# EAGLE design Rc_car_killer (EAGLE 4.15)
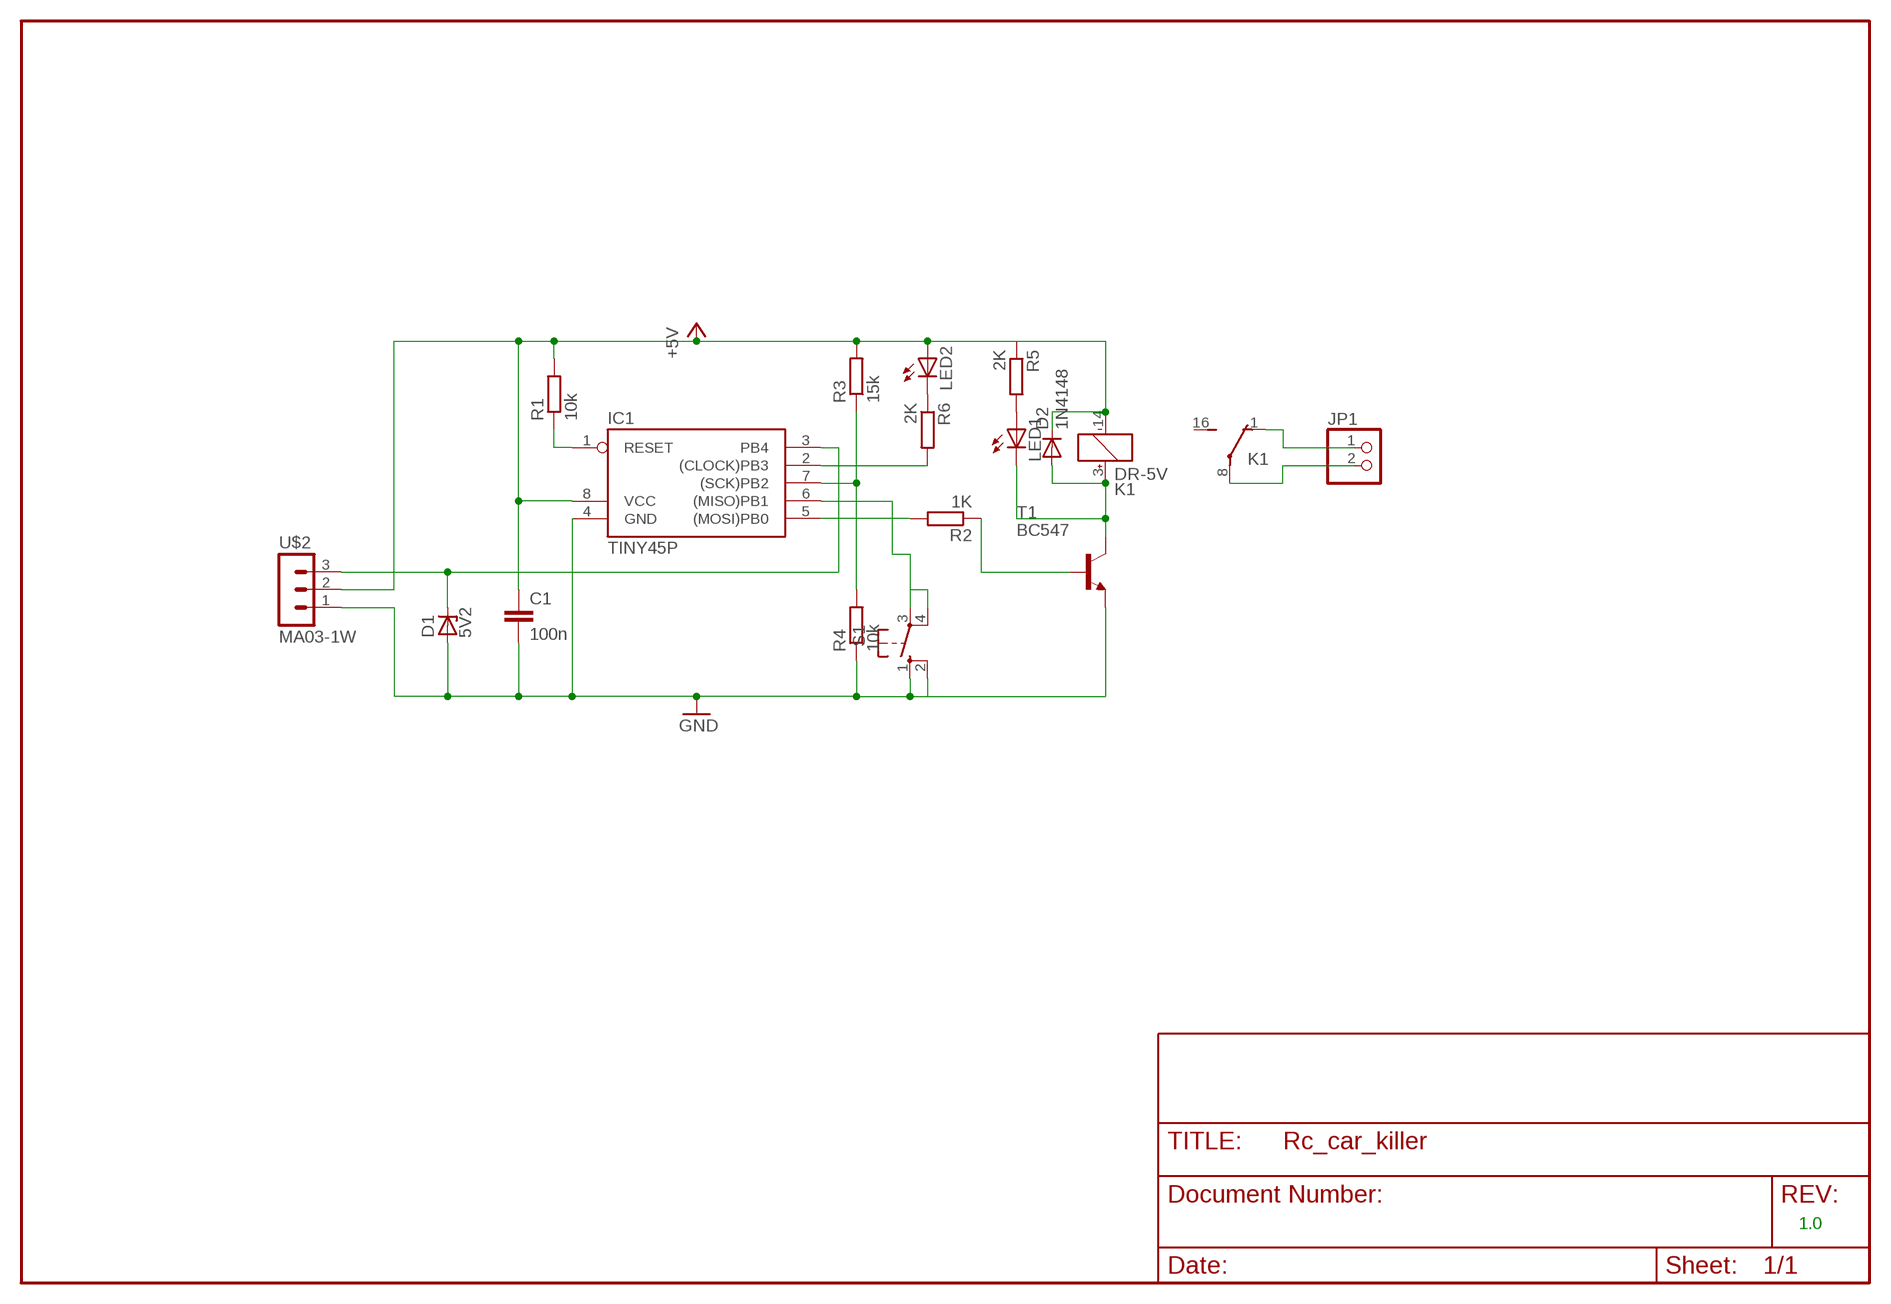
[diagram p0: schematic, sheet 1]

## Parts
C1  100n  C-EU025-025X050  [C025-025X050]
D1  5V2  ZENER-DIODEZD-7.5  [ZDIO-7.5]
D2  1N4148  [DO35-10]
IC1  TINY45P  [DIL08]
JP1  PINHD-1X2  [1X02]
K1  DR-5V  [DR-1]
LED1  LED3MM  [LED3MM]
LED2  LED3MM  [LED3MM]
R1  10k  R-EU_  [0207/10_GROOT]
R2  1K  R-EU_  [0207/10_GROOT]
R3  15k  R-EU_  [0207/10_GROOT]
R4  10k  R-EU_  [0207/10_GROOT]
R5  2K  R-EU_  [0207/10_GROOT]
R6  2K  R-EU_  [0207/10_GROOT]
S1  10-XX-REVERSED  [B3F-10XX]
T1  BC547  [TO92]
U$2  MA03-1W  [MA03-1W]

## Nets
+5V [Vcc]: C1.1 D2.C IC1.8(VCC) K1.14(-1:-) LED2.A R1.2 R3.2 R5.1 U$2.2
GND [gnd]: C1.2 D1.A IC1.4(GND) R4.1 S1.1(S) S1.2(S1) T1.1(E) U$2.1
N$1: IC1.7((SCK)PB2) R3.1 R4.2
N$2: IC1.1(RESET) R1.1
N$3: IC1.5((MOSI)PB0) R2.2
N$4: LED1.A R5.2
N$5: IC1.6((MISO)PB1) S1.3(P) S1.4(P1)
N$6: D1.C IC1.3(PB4) U$2.3
N$8: D2.A K1.3(-1:+) LED1.K(C) T1.3(C)
N$9: LED2.K(C) R6.1
N$10: IC1.2((CLOCK)PB3) R6.2
N$11: R2.1 T1.2(B)
N$12: JP1.2 K1.8(-2:P)
N$13: JP1.1 K1.1(-2:O)
Unconnected: K1.16(-2:S)

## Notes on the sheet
- 1.0

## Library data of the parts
C1 = rcl:C-EU: CAPACITOR, European symbol
D1 = diode:ZENER-DIODE: Z-Diode
D2 = diode:1N4148: DIODE
IC1 = Evert:TINY45: MICROCONTROLLER 1K ROM 128 bytes RAM 128 bytes EEPROM
JP1 = pinhead:PINHD-1X2: PIN HEADER
K1 = relay:DR-*V: HIGHLY RELIABLE MINIATURE DIP RELAYS NAiS Source: www.mew-europe.com/ac/download/ datasheet/relay/dr_en.pdf
LED1 LED2 = led:LED: LED
R1-R6 = rcl:R-EU_: RESISTOR, European symbol
S1 = Evert:10-XX-REVERSED: OMRON SWITCH
T1 = transistor:BC547: NPN TRANSISTOR
U$2 = con-lstb:MA03-1W

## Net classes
0 default: width 0.61 mm, drill 0.051 mm
1 Vcc: width 0.5 mm, drill 0.051 mm
2 gnd: width 0.2 mm, drill 0.051 mm

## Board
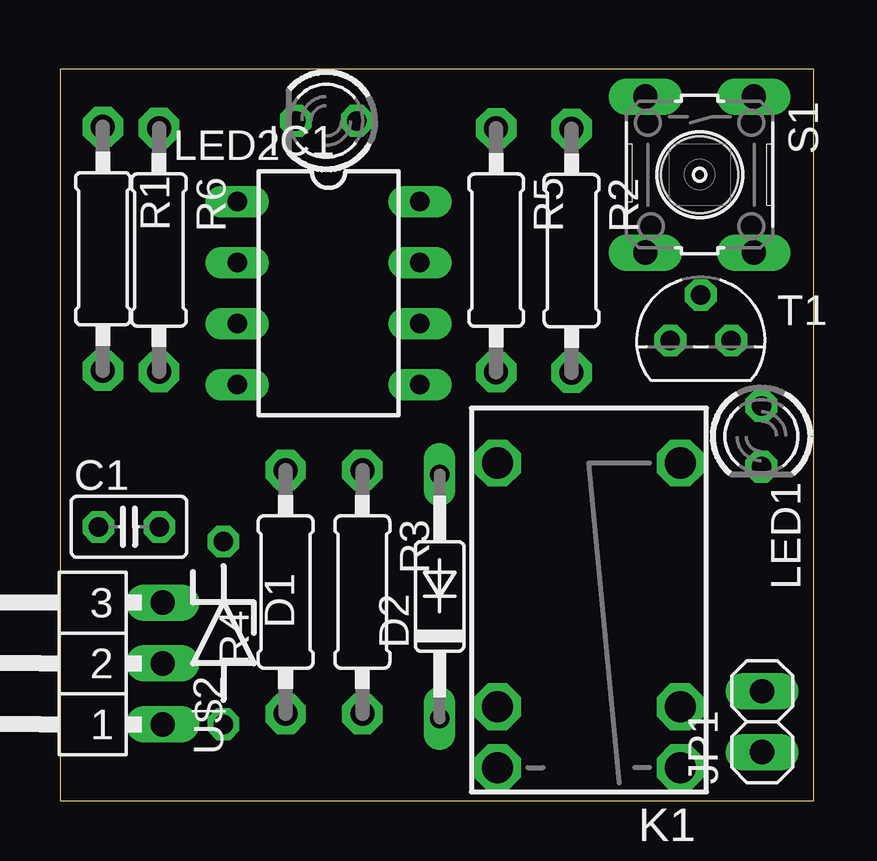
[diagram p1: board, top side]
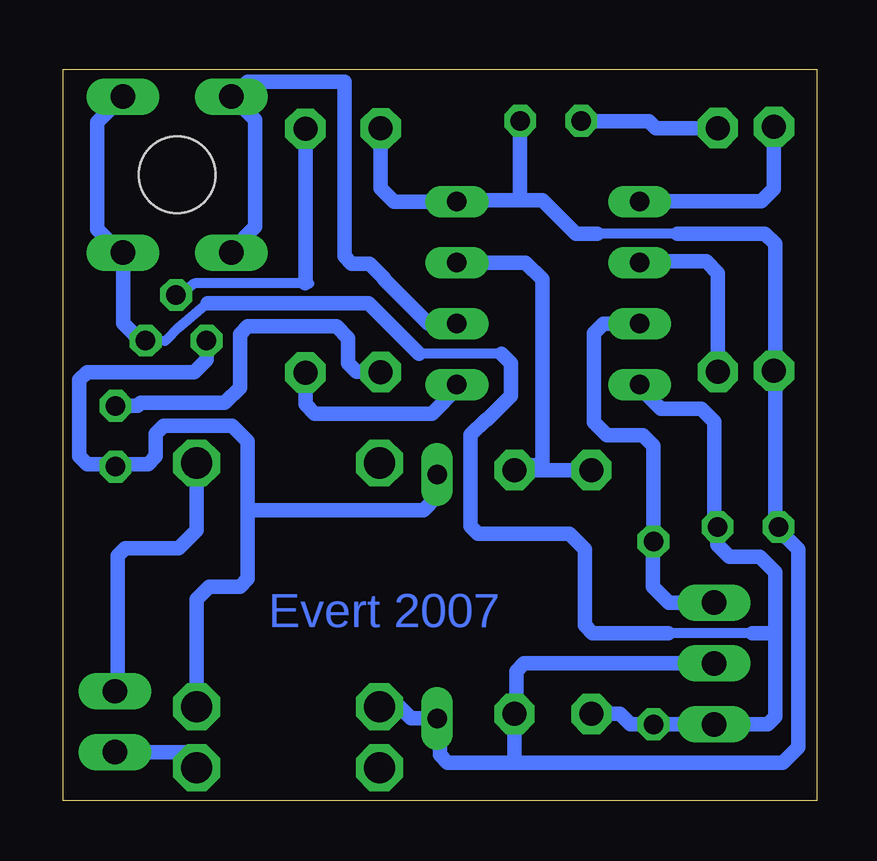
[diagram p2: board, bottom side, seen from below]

Size 31.42 x 30.47 mm. Coordinates in mm from the lower left corner, seen from the top.
Outline: 0,0 31.42,0 31.42,30.47 0,30.47 0,0
Copper layers (1*16): Top 0.035mm / dielectric 1.5mm / Bottom 0.035mm
Design rules "default": minimum track width 10mil, minimum drill 24mil, track to track 8mil, track to pad 8mil, pad to pad 8mil, via to via 8mil, smd to smd 8mil, copper to edge 20mil, drill to drill 8mil, minimum pad ring 10mil, minimum via ring 8mil, stop-mask expansion 4mil, vias tented up to drill 0mil, thermal gap 10mil

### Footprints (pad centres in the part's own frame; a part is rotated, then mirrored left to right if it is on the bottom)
C025-025X050 = drill 0.813 octagon: 1 -1.27,0; 2 1.27,0
ZDIO-7.5 = drill 0.813 octagon: A 3.81,0; C -3.81,0
DO35-10 = drill 0.813 long: A 5.08,0; C -5.08,0
DIL08 = drill 0.813 long: 1 -3.81,-3.81; 2 -1.27,-3.81; 3 1.27,-3.81; 4 3.81,-3.81; 5 3.81,3.81; 6 1.27,3.81; 7 -1.27,3.81; 8 -3.81,3.81
1X02 = drill 1.016 long: 1 -1.27,0; 2 1.27,0
DR-1 = drill 1.3 octagon: 1 -8.89,-3.81; 3 -6.35,-3.81; 8 3.81,-3.81; 9 3.81,3.81; 14 -6.35,3.81; 16 -8.89,3.81
LED3MM = drill 0.813 octagon: A -1.27,0; K 1.27,0
0207/10_GROOT = drill 1 pad 1.676 octagon: 1 -5.08,0; 2 5.08,0
B3F-10XX = drill 1.016 long: 1 -3.251,2.261; 2 3.251,2.261; 3 -3.251,-2.261; 4 3.251,-2.261 | hole 3.2: 0,0
TO92 = drill 0.813 octagon: 1 1.27,0; 2 0,1.905; 3 -1.27,0
MA03-1W = drill 1.016 long: 1 -2.54,0; 2 0,0; 3 2.54,0

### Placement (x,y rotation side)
C1  2.88,11.4 0 top
D1  6.81,6.99 270 top
D2  15.83,8.5 90 top
IC1  11.2,21.14 270 top
JP1  29.27,3.28 90 top
K1  22.05,10.26 90 top
LED1  29.24,15.18 270 top
LED2  11.1,28.32 180 top
R1  1.79,22.99 270 top
R2  21.33,22.91 270 top
R3  12.61,8.69 270 top
R4  9.41,8.69 90 top
R5  18.19,22.93 270 top
R6  4.13,22.94 270 top
S1  26.67,26.08 270 top
T1  26.72,19.16 0 top
U$2  4.28,5.71 90 top

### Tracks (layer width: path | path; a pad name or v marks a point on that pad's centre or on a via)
+5V
  Bottom 0.406: 5.81,23.61 9.16,23.61
  Bottom 0.61: 1.72,11.4 C1.1 | 1.72,11.4 1.74,11.43 | 1.72,11.4 0.79,10.47 0.79,2.22 1.42,1.58 12.54,1.58 | 12.54,1.58 15.39,1.58 15.71,1.9 15.71,3.3 D2.C 16.92,3.42 17.4,3.91 18.22,3.91 18.23,3.89 K1.14 | 12.54,1.58 12.61,1.65 R3.2 12.61,3.56 12.54,3.49 12.54,5.39 12.22,5.71 U$2.2 | R1.2 1.78,17.25 1.76,17.22 1.74,17.24 | C1.1 | 1.74,17.24 1.74,11.54 C1.1 | 1.74,17.24 1.74,23.19 2.17,23.61 5.81,23.61 | 9.16,23.61 10.06,23.61 11.45,25.01 12.3,25.01 | IC1.8 15.05,24.91 | IC1.8 17.63,24.95 18.19,25.51 18.19,27.96 18.19,27.97 R5.1 | 12.3,25.01 14.95,25.01 IC1.8 | 12.3,25.01 12.3,25.11 12.37,25.18 LED2.A
GND
  Bottom 0.406: S1.2 29.04,22.83 | 27.88,19.12 27.93,19.16 T1.1 27.18,19.14 26.58,19.73 26.64,19.68 25.4,20.71 | 2.69,6.98 6.18,6.98 | 16.56,18.62 16.6,18.62 | 13.15,18.62 16.56,18.62 | 16.56,18.62 16.56,18.6
  Bottom 0.61: S1.1 30,28.25 30,23.81 29.02,22.83 S1.2 28.93,19.88 28.09,19.04 T1.1 | 6.18,6.98 9.36,6.98 9.68,7.3 9.68,10.47 10.31,11.11 14.12,11.11 14.44,11.43 14.44,15.24 13.81,15.87 13.75,15.87 12.75,16.87 12.75,18.22 13.15,18.62 | R4.1 8.21,3.61 7.77,3.17 D1.A U$2.1 2.06,3.17 1.74,3.49 1.74,6.98 | 1.74,6.98 1.74,9.52 2.38,10.16 3.64,10.16 4.14,10.66 C1.2 4.26,11.4 4.28,11.43 4.28,15.79 4.81,16.32 6.51,16.32 7.39,17.2 IC1.4 | 1.74,6.98 2.69,6.98 | 25.4,20.71 18.69,20.71 16.6,18.62
N$1
  Bottom 0.61: 12.54,13.97 12.61,13.89 R3.1 | R4.2 12.34,13.77 12.54,13.97 | 12.54,13.97 11.45,13.97 11.45,21.71 12.15,22.41 14.95,22.41 15,22.36 15.01,22.37 IC1.7
N$2
  Bottom 0.61: R1.1 1.79,25.49 2.32,24.96 7.31,24.96 7.32,24.95 IC1.1
N$3
  Bottom 0.61: R2.2 21.33,16.51 20.94,16.12 16.05,16.12 15,17.17 15.01,17.18 IC1.5
N$4
  Bottom 0.61: LED1.A 28.32,16.45 28.2,16.57 24.7,16.57 24.06,17.2 24.06,19.44 23.74,19.75 20.03,19.75 19.54,19.27 19.54,18.22 19.19,17.87 18.19,17.87 R5.2
N$5
  Bottom 0.61: 24.38,29.32 24.39,29.33 S1.3 | 24.38,29.32 23.74,29.95 19.7,29.95 19.7,22.67 19.39,22.36 18.64,22.36 18.04,21.77 18.04,21.71 17.54,21.21 | 24.38,29.32 | 24.38,29.32 23.42,28.36 23.42,23.9 24.41,22.91 S1.4 | IC1.6 16.2,19.87 17.54,21.21 | 17.54,21.21
N$6
  Bottom 0.61: U$2.3 6.18,8.25 6.84,8.92 6.84,10.83 D1.C 6.81,14.77 7.26,15.22 8.76,15.22 9.31,15.77 9.31,19.47 8.91,19.87 7.36,19.87 IC1.3
N$8
  Bottom 0.61: K1.3 25.86,8.39 25.33,8.92 24.06,8.92 23.74,9.24 23.74,12.11 | 23.74,12.11 23.74,14.97 24.38,15.61 27.24,15.61 27.56,15.29 27.56,14.34 27.88,14.02 29.16,14.02 | D2.A 15.83,12.68 16.41,12.11 23.74,12.11 | T1.3 25.45,18.36 25.97,17.84 30.43,17.84 30.75,17.52 30.75,14.34 30.43,14.02 29.16,14.02 | 29.16,14.02 29.24,13.93 LED1.K
N$9
  Bottom 0.61: R6.1 6.72,28.02 7.01,28.31 9.76,28.31 9.77,28.32 LED2.K
N$10
  Bottom 0.61: R6.2 4.13,21.98 4.61,22.46 7.31,22.46 7.36,22.41 IC1.2
N$11
  Bottom 0.406: T1.2 26.64,21.07 26.61,21.03 25.95,21.55 21.34,21.55 21.16,21.55
  Bottom 0.61: 21.34,21.55 21.34,21.71 21.33,21.72 R2.1
N$12
  Bottom 0.61: K1.8 25.86,11.26 26.61,10.51 28.84,10.51 29.16,10.19 29.16,4.46 29.26,4.55 JP1.2
N$13
  Bottom 0.61: 25.97,1.37 25.97,1.27 | K1.1 25.97,1.37 | JP1.1 25.97,2.02 25.97,1.37

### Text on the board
Bottom: Evert 2007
